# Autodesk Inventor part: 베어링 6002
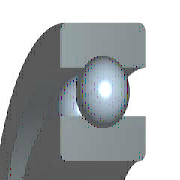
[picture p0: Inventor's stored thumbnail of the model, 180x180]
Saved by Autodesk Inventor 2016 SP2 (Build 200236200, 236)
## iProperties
Created: 2012-02
Part Number: 베어링 6002
Material: 강철, 연강
Description: 깊은 그루브 볼 베어링
Document SubType Name: Modeling
Standard: KS B 2023
Designer: mduedu
Standards Organization: KS
Language: ko-KR
Size Designation: 6002 - 15 x 32 x 9
Categories: <MemberInstance><Categories><Category DisplayName="샤프트 부품" InternalName="7f7aeb1f-a693-4053-b835-cee3144e0d98" Mnemonic="SHFT"><Category DisplayName="베어링" Inter
Density: 1 g/cm^3
Appearance: 노란색
IsCustomPart: 1
Author: mduedu
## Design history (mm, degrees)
sketch "스케치" dims "d0" = 4.42 (= -0.26 x WD + 0.26 x BD)
  geometry: L1 (2.29, 11.75)-(6.71, 11.75); L2 (4.5, 11.75)-(4.5, 9.54); L3 (4.5, 11.75)-(4.5, 13.96); L4 (2.858, 10.271)-(0, 10.271); L5 (0, 7.5)-(9, 7.5); L6 (2.858, 13.229)-(0, 13.229); L7 (0, 16)-(9, 16); L8 (9, 7.5)-(9, 10.271); L9 (6.142, 10.271)-(9, 10.271); L10 (6.142, 13.229)-(9, 13.229); L11 (9, 16)-(9, 13.229); L12 (-1.4, 0)-(8.4, 0) reference; L13 (0, -0.3)-(0, 5.3) reference
  constraints: 22 end point, 4 point on line, 2 collinear, 2 perpendicular, 2 symmetric about line, 1 midpoint, 1 parallel, 14 other
  dimensions: "d9" = 15 diameter of L5 L12 (= WD); "d11" = 32 diameter of L7 L12 (= BD); "d12" = 9 distance between parallel lines of L8 L13 (= KB); "d13" = 20.542 diameter of L9 L12 (= 0.326 x BD + 0.674 x WD)
revolve "본체" stored, may be unused: angle "d6" = 90 deg
revolve "볼" stored, may be unused: angle "d7" = 90 deg
pattern_circular "IDS_ARRAYBALL[SIMPL:T]" dims angle "d3" = 360 deg
body "Solid1"
fillet "모깎기1" dims "d1" = 0.3 (= KRS)
other parameters: "WD" = 15 [user parameter; used in 5 equation terms], "BD" = 32 [user parameter; used in 5 equation terms], "KB" = 9 [user parameter; used in 1 equation term], "KRS" = 0.3 [user parameter; used in 1 equation term], "d4" = 0, "d5" = 0, "d8" = 0, "d14" = 0, "d15" = 0, "BBA" = 0 [user parameter], "BC0" = 2850000 [user parameter], "BC" = 5590000 [user parameter], "BR" = 16 (= 0.5 x BD) [user parameter], "WR" = 7.5 (= 0.5 x WD) [user parameter]
